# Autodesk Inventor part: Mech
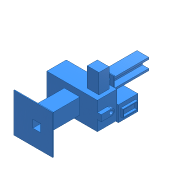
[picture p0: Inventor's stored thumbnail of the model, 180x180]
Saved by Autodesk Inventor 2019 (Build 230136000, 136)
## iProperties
Created: 2018-04
Part Number: Mech
Material: 一般
Document SubType Name: Modeling
Designer: ADJ
Density: 1 g/cm^3
Appearance: シアン
Mass: 107451 g
Surface Area: 33551.2 cm^2
Volume: 107451 cm^3
Author: ADJ
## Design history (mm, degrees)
sketch "スケッチ1"
  geometry: L1 (250, 250)-(-250, 250); L2 (-250, 250)-(-250, -250); L3 (-250, -250)-(250, -250); L4 (250, -250)-(250, 250); L5 (250, 250)-(-250, -250); L6 (-250, 250)-(250, -250); L7 (100, 100)-(-100, 100); L8 (-100, 100)-(-100, -100); L9 (-100, -100)-(100, -100); L10 (100, -100)-(100, 100); L11 (100, 100)-(-100, -100); L12 (-100, 100)-(100, -100); 1 further point
  constraints: 24 end point, 4 midpoint, 4 parallel, 2 horizontal, 2 perpendicular
  dimensions: "d0" = 500 distance of L3.end L2.end; "d1" = 500 distance of L2.end L1.end; "d4" = 200 distance of L9.end L8.end; "d5" = 200 distance of L8.end L7.end
extrude "押し出し1" new body sketch "スケッチ1" distance "d2" = 10; taper "d3" = 0 deg
extrude "押し出し2" join sketch "スケッチ1" distance "d6" = 500; taper "d7" = 0 deg
sketch "スケッチ2"
  geometry: L1 (-325, -175)-(325, -175); L2 (325, -175)-(325, 175); L3 (325, 175)-(-325, 175); L4 (-325, 175)-(-325, -175); L5 (-325, -175)-(325, 175); L6 (325, -175)-(-325, 175); 1 further point
  constraints: 12 end point, 2 midpoint, 2 parallel, 1 horizontal, 1 perpendicular
  dimensions: "d8" = 350 distance of L1.end L2.end; "d9" = 650 distance of L2.end L3.end
extrude "押し出し3" join sketch "スケッチ2" distance "d10" = 250; taper "d11" = 0 deg
sketch "スケッチ3"
  geometry: L1 (650, 0)-(650, 250) reference; L2 (0, 250)-(650, 250) reference; L3 (450, 200)-(600, 200); L4 (600, 200)-(600, 70); L5 (600, 70)-(450, 70); L6 (450, 70)-(450, 200); L7 (450, 200)-(600, 70); L8 (600, 200)-(450, 70); 2 further points
  constraints: 12 end point, 2 midpoint, 2 parallel, 1 horizontal, 1 perpendicular
  dimensions: "d12" = 150 distance of L4.end L5.end; "d13" = 130 distance of L3.end L4.end; "d14" = 50 distance between parallel lines of L2 L3; "d15" = 50 distance between parallel lines of L1 L4
extrude "押し出し4" join sketch "スケッチ3" distance "d16" = 250; taper "d17" = 0 deg
sketch "スケッチ4"
  geometry: L1 (0, 0)-(350, 0) reference; L2 (0, 0)-(0, 250) reference; L3 (215, 130)-(215, 0); L4 (135, 130)-(135, 0); A1 r 40 centre (175, 130) between (215, 130) and (135, 130); 1 further point
  constraints: 4 end point, 2 perpendicular, 2 point on circle, 2 point on line, 2 tangent, 1 centre point
  dimensions: "d18" = 80 diameter of A1; "d19" = 130 distance from line of L1 A1.centre; "d20" = 175 distance from line of A1.centre L2
extrude "押し出し5" join sketch "スケッチ4" distance "d21" = 50; taper "d22" = 0 deg
hole "穴1" diameter "d25" = 50; stored, may be unused: countersink angle "d29" = 90 deg, drill point angle "d31" = 118 deg; dims "d23" = 10, "d24" = 10, "d26" = 6, "d27" = 4, "d28" = 2, "d30" = 100
sketch "スケッチ5"
  geometry: L1 (-100, -100)-(100, -100); L2 (100, -100)-(100, 100); L3 (100, 100)-(-100, 100); L4 (-100, 100)-(-100, -100); L5 (-100, -100)-(100, 100); L6 (100, -100)-(-100, 100); 1 further point
  constraints: 12 end point, 2 midpoint, 2 parallel, 1 horizontal, 1 perpendicular
  dimensions: "d32" = 200 distance of L3.end L2.end; "d33" = 200 distance of L2.end L1.end
extrude "押し出し6" join sketch "スケッチ5" distance "d34" = 150; taper "d35" = 0 deg
sketch "スケッチ6"
  geometry: L1 (-100, -100)-(100, -100) reference; L2 (-100, 100)-(-100, -100) reference; L3 (135, -150)-(-135, -150); L4 (-135, -150)-(-135, 350); L5 (-135, 350)-(135, 350); L6 (135, 350)-(135, -150); 1 further point
  constraints: 8 end point, 2 parallel, 1 horizontal, 1 perpendicular
  dimensions: "d36" = 500 distance of L3.end L4.end; "d37" = 270 distance of L4.end L5.end; "d38" = 35 distance between parallel lines of L4 L2; "d39" = 50 distance between parallel lines of L1 L3
extrude "押し出し7" join sketch "スケッチ6" distance "d40" = 10; taper "d41" = 0 deg
sketch "スケッチ7"
  geometry: L1 (135, -150)-(135, 350) reference; L2 (135, 350)-(-135, 350) reference; L3 (-165, 150)-(185, 150); L4 (185, 150)-(185, 350); L5 (185, 350)-(-165, 350); L6 (-165, 350)-(-165, 150); 1 further point
  constraints: 8 end point, 2 parallel, 1 collinear, 1 horizontal, 1 perpendicular
  dimensions: "d42" = 200 distance of L5.end L3.start; "d43" = 50 distance between parallel lines of L1 L4; "d44" = 350 distance of L4.end L5.end
extrude "押し出し8" join sketch "スケッチ7" distance "d45" = 250; taper "d46" = 0 deg
sketch "スケッチ8"
  geometry: L1 (0, 0)-(200, 0) reference; L2 (200, 0)-(200, 250) reference; L3 (0, 250)-(200, 250) reference; L4 (0, 0)-(0, 250) reference; L5 (60, 210)-(140, 210); L6 (140, 210)-(140, 40); L7 (140, 40)-(60, 40); L8 (60, 40)-(60, 210); L9 (60, 210)-(140, 40); L10 (140, 210)-(60, 40); L11 (150, 220)-(50, 220); L12 (50, 220)-(50, 30); L13 (50, 30)-(150, 30); L14 (150, 30)-(150, 220); 2 further points
  constraints: 20 end point, 4 parallel, 2 midpoint, 2 perpendicular, 1 horizontal, 3 other
  dimensions: "d47" = 10 distance between parallel lines of L11 L5; "d48" = 30 distance between parallel lines of L3 L11; "d49" = 50 distance between parallel lines of L2 L14; "d50" = 50 distance between parallel lines of L12 L4; "d51" = 30 distance between parallel lines of L1 L13
extrude "押し出し9" join sketch "スケッチ8" distance "d52" = 30; taper "d53" = 0 deg
sketch "スケッチ9"
  geometry: L1 (-75, -75)-(75, -75); L2 (75, -75)-(75, 75); L3 (75, 75)-(-75, 75); L4 (-75, 75)-(-75, -75); L5 (-75, -75)-(75, 75); L6 (75, -75)-(-75, 75); 1 further point
  constraints: 12 end point, 2 midpoint, 2 parallel, 1 horizontal, 1 perpendicular
  dimensions: "d54" = 150 distance of L3.end L2.end; "d55" = 150 distance of L2.end L1.end
extrude "押し出し10" join sketch "スケッチ9" distance "d56" = 500; taper "d57" = 0 deg
sketch "スケッチ10"
  geometry: L1 (95, 50)-(-5, 50); L2 (-5, 50)-(-5, -50); L3 (-5, -50)-(95, -50); L4 (95, -50)-(95, 50); L5 (95, 50)-(-5, -50); L6 (-5, 50)-(95, -50); L7 (-250, 250)-(250, 250) reference; L8 (250, 250)-(250, -250) reference
  constraints: 12 end point, 2 parallel, 1 horizontal, 1 perpendicular
  dimensions: "d58" = 100 distance of L3.end L2.end; "d59" = 100 distance of L2.end L1.end; "d62" = 155 distance between parallel lines of L8 L4; "d63" = 200 distance between parallel lines of L7 L1
extrude "押し出し11" cut sketch "スケッチ10" extent not by distance; stored distance "d60" = 1200; taper "d61" = 0 deg
node "ソリッド1"
feature "耀䁁"
